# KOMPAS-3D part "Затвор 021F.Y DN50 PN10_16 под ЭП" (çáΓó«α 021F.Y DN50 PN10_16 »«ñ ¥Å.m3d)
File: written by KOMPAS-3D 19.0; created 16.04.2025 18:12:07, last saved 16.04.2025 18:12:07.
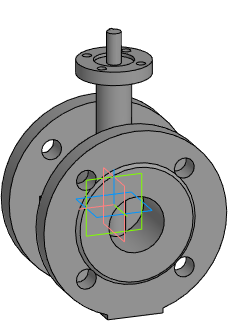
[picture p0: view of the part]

Document properties: Автор: Евгений; Полное имя файла: E:\Dendor Работа Сачек\3D для проекитирвщиков\1.6 Тип 021F.Y Затвор дисковый поворотный фланцевый\stp_Тип 021F.Y Затвор  DN40 PN10_16 под ЭП\Затвор 021F.Y DN50 PN10_16 под ЭП.m3d

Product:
- Part/product: Затвор 021F.Y DN50 PN10_16 под ЭП

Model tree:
1. Операция без истории:1  (labels: Затвор 021F.Y DN50 PN10_16 под ЭП)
